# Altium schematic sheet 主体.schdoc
size 297 x 209 mm; Symbol: Drawing-Symbol_A4; @Create Time: 10:59:36; @Update Time: 20:11:28; Border: 1; Width: 1170; Height: 825; Region Start: 1; X Region Count: 6; Y Region Count: 4; Blade Width: 10; Title Block Position: 3; Title Block: 1; @Board Name: Board1; Company: 嘉立创EDA; Version: V1.0; Page Size: A4; @Project Name: stm32f4; @Page Count: 3; @Update Date: 2025-11-17; @Create Date: 2025-10-30; @Schematic Name: Schematic1; @Page No: 1; @Page Name: 主体; Device: Drawing-Symbol_A4
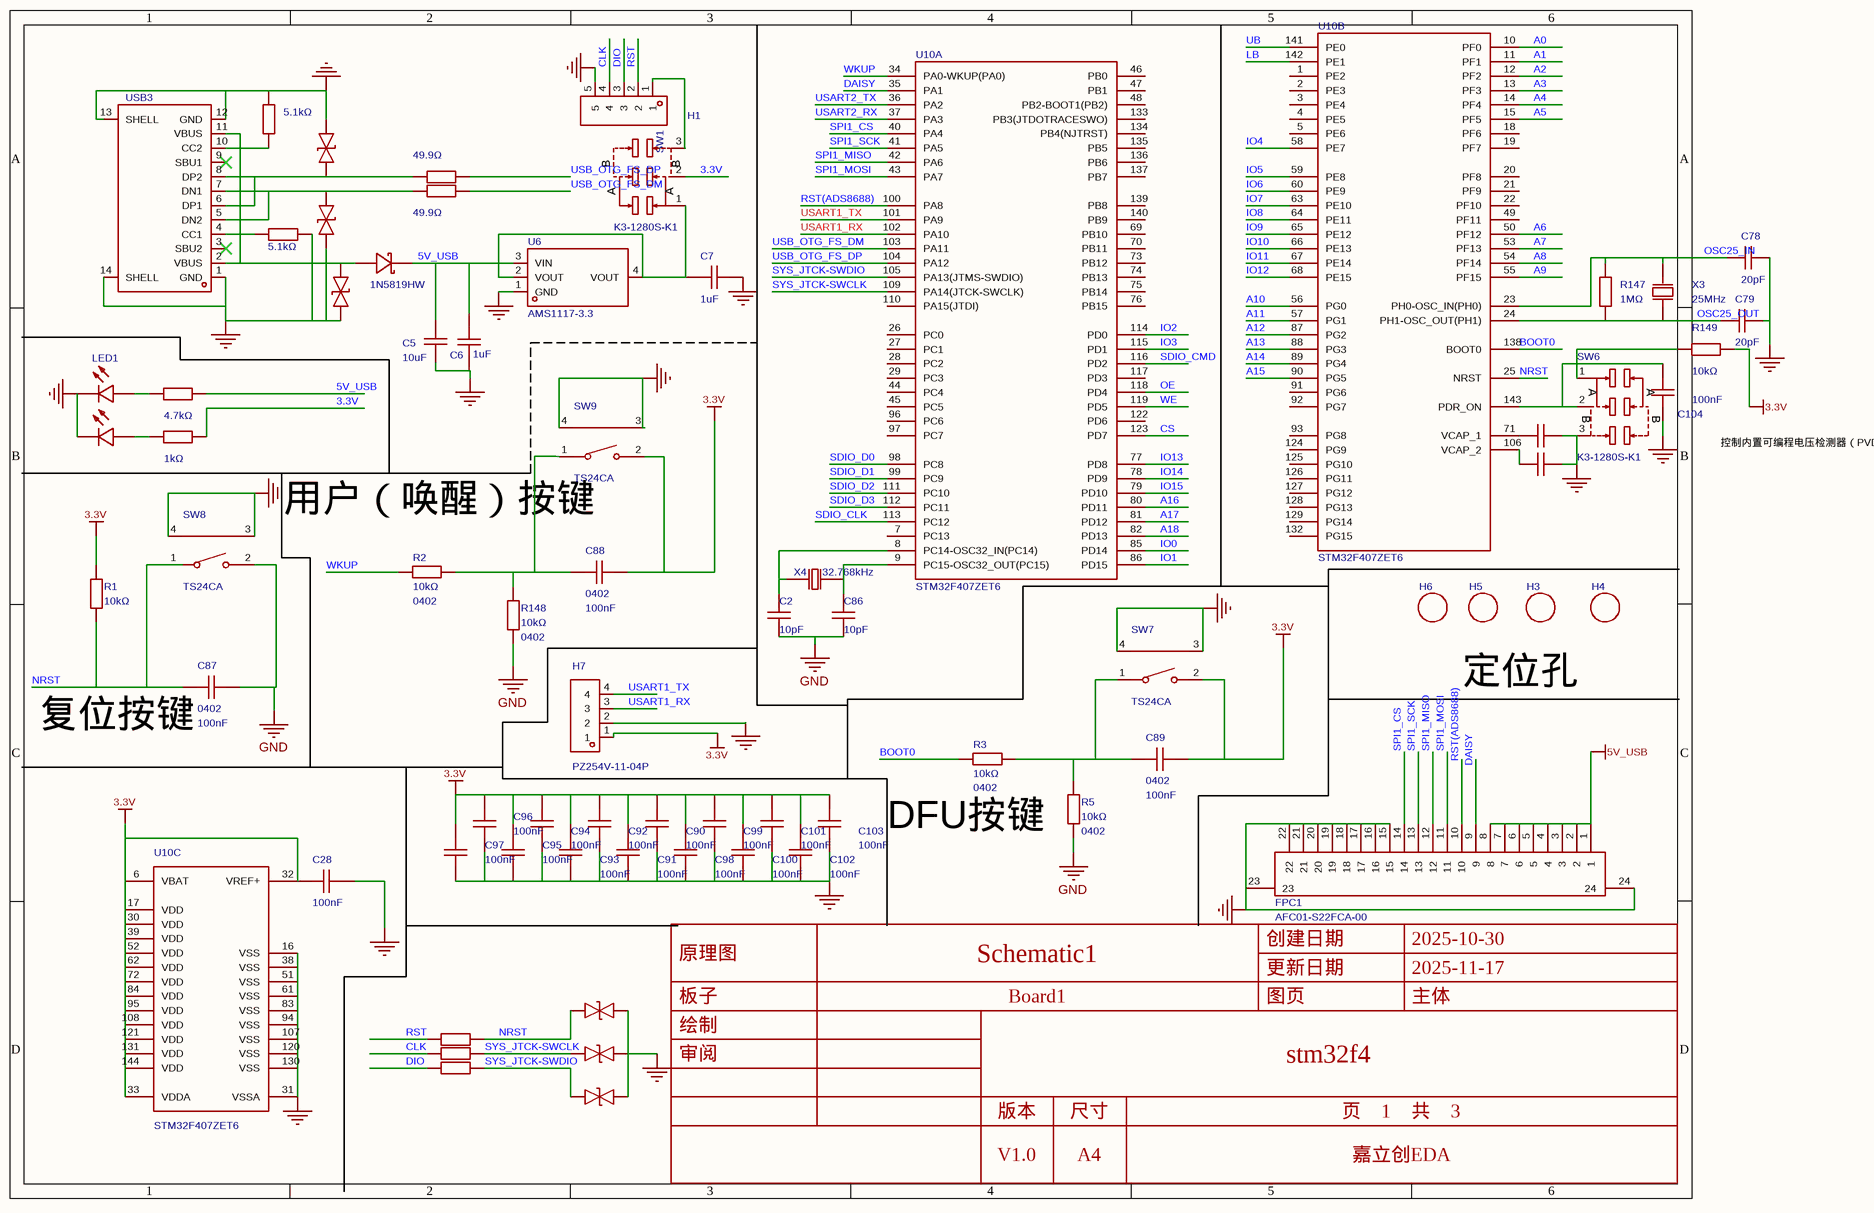
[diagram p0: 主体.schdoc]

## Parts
C2  value 10pF  [r0402]
C5  10uF  [C0603]
C6  1uF  [C0603]
C7  1uF  [C0603]
C28  100nF  [C0603]
C78  20pF  [C0603]
C79  20pF  [C0603]
C80  2.2uF  [C0603]  (value not drawn)
C81  2.2uF  [C0603]  (value not drawn)
C86  value 10pF  [r0402]
C87  value 100nF  Supplier Footprint: 0402  [C0402]  (hidden comment: CC0402KRX7R7BB104)
C88  value 100nF  Supplier Footprint: 0402  [C0402]  (hidden comment: CC0402KRX7R7BB104)
C89  value 100nF  Supplier Footprint: 0402  [C0402]  (hidden comment: CC0402KRX7R7BB104)
C90  100nF  [C0402]
C91  100nF  [C0402]
C92  100nF  [C0402]
C93  100nF  [C0402]
C94  100nF  [C0402]
C95  100nF  [C0402]
C96  100nF  [C0402]
C97  100nF  [C0402]
C98  100nF  [C0402]
C99  100nF  [C0402]
C100  100nF  [C0402]
C101  100nF  [C0402]
C102  100nF  [C0402]
C103  100nF  [C0402]
C104  100nF  [C0402]
D9  0603ESDA-05N  [D0603-BI]  (value not drawn)
D10  0603ESDA-05N  [D0603-BI]  (value not drawn)
D11  0603ESDA-05N  [D0603-BI]  (value not drawn)
D13  LESD5D5.0CT1G  [SOD-523_L1.2-W0.8-LS1.6-BI]  (value not drawn)
D14  LESD5D5.0CT1G  [SOD-523_L1.2-W0.8-LS1.6-BI]  (value not drawn)
D15  LESD5D5.0CT1G  [SOD-523_L1.2-W0.8-LS1.6-BI]  (value not drawn)
D16  1N5819HW  [SOD-123_L2.7-W1.6-LS3.7-RD-1]
FPC1  AFC01-S22FCA-00  [FPC-SMD_P0.5-22P_FGS-XJ-H2.0]
H1  PZ254V-11-05P  [HDR-TH_5P-P2.54-V-M]  (value not drawn)
H3  m3_3  [m3 125x300]  (value not drawn)
H4  m3_3  [m3 125x300]  (value not drawn)
H5  m3_3  [m3 125x300]  (value not drawn)
H6  m3_3  [m3 125x300]  (value not drawn)
H7  PZ254V-11-04P  [HDR-TH_4P-P2.54-V-M]
LED1  19-217/R6C-AL1M2VY/3T  [LED0603-RD]  (value not drawn)
LED5  19-213/Y2C-CQ2R2L/3T(CY)  [LED0603-RD-YELLOW]  (value not drawn)
R1  value 10kΩ  [R0402]  (hidden comment: RC0402FR-0710KL)
R2  value 10kΩ  Supplier Footprint: 0402  [R0402]  (hidden comment: RC0402FR-0710KL)
R3  value 10kΩ  Supplier Footprint: 0402  [R0402]  (hidden comment: RC0402FR-0710KL)
R5  value 10kΩ  Supplier Footprint: 0402  [R0402]  (hidden comment: RC0402FR-0710KL)
R7  49.9Ω  [R0603]  (value not drawn)
R8  49.9Ω  [R0603]  (value not drawn)
R9  49.9Ω  [R0603]  (value not drawn)
R21  value 49.9Ω  [R0603]  (hidden comment: 0603WAF499JT5E)
R22  value 49.9Ω  [R0603]  (hidden comment: 0603WAF499JT5E)
R24  5.1kΩ  [R0402]
R25  5.1kΩ  [R0402]
R26  4.7kΩ  [R0402]
R27  1kΩ  [R0402]
R147  1MΩ  [R0603]
R148  value 10kΩ  Supplier Footprint: 0402  [R0402]  (hidden comment: RC0402FR-0710KL)
R149  10kΩ  [R0402]
SW1  K3-1280S-K1  [SW-SMD_K3-1280S-K1]
SW6  K3-1280S-K1  [SW-SMD_K3-1280S-K1]
SW7  TS24CA  [SW-SMD_2P-TS24CA]
SW8  TS24CA  [SW-SMD_2P-TS24CA]
SW9  TS24CA  [SW-SMD_2P-TS24CA]
U6  AMS1117-3.3  [SOT-223-3_L6.5-W3.4-P2.30-LS7.0-BR]
U10  STM32F407ZET6  [LQFP-144_L20.0-W20.0-P0.50-LS22.0-BL]  (parts A,B,C of 3)
USB3  TYPE-C 16PIN 2MD(073)  [USB-C-SMD_TYPE-C-6PIN-2MD-073]  (value not drawn)
X3  25MHz  [OSC-SMD_L5.0-W3.2]
X4  value 32.768kHz  [crystal-smd_l3.2-w1.5-1]

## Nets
3.3V: C28.1 C88.1 C89.1 C90.1 C91.1 C92.1 C93.1 C94.1 C95.1 C96.1 C97.1 C98.1 C99.1 C100.1 C101.1 C102.1 C103.1 H7.1 R1.1 R27.2 R149.2 SW1.2 SW7.2 SW9.2 U10.6(VBAT) U10.17(VDD) U10.30(VDD) U10.32(VREF+) U10.33(VDDA) U10.39(VDD) U10.52(VDD) U10.62(VDD) U10.72(VDD) U10.84(VDD) U10.95(VDD) U10.108(VDD) U10.121(VDD) U10.131(VDD) U10.144(VDD)
5V_USB: C5.2 C6.2 D16.1(K) FPC1.1 FPC1.2 FPC1.3 FPC1.4 FPC1.5 FPC1.6 FPC1.7 FPC1.8 R26.2 U6.3(VIN)
GND: C2.1 C5.1 C6.1 C7.2 C28.2 C78.1 C79.1 C80.2 C81.2 C86.1 C87.1 C90.2 C91.2 C92.2 C93.2 C94.2 C95.2 C96.2 C97.2 C98.2 C99.2 C100.2 C101.2 C102.2 C103.2 C104.1 D9.2 D10.2 D11.2 D13.1 D14.1 D15.1 FPC1.15 FPC1.16 FPC1.17 FPC1.18 FPC1.19 FPC1.20 FPC1.21 FPC1.22 FPC1.23 FPC1.24 H1.5 H7.2 LED1.1(C) LED5.1(C) R5.2 R24.2 R25.2 R148.2 SW6.3 SW7.3 SW7.4 SW8.2 SW8.3 SW8.4 SW9.3 SW9.4 U6.1(GND) U10.16(VSS) U10.31(VSSA) U10.38(VSS) U10.51(VSS) U10.61(VSS) U10.83(VSS) U10.94(VSS) U10.107(VSS) U10.120(VSS) U10.130(VSS) USB3.1(GND) USB3.12(GND) USB3.13(SHELL) USB3.14(SHELL)
A0: U10.10(PF0)
A1: U10.11(PF1)
A2: U10.12(PF2)
A3: U10.13(PF3)
A4: U10.14(PF4)
A5: U10.15(PF5)
A6: U10.50(PF12)
A7: U10.53(PF13)
A8: U10.54(PF14)
A9: U10.55(PF15)
A10: U10.56(PG0)
A11: U10.57(PG1)
A12: U10.87(PG2)
A13: U10.88(PG3)
A14: U10.89(PG4)
A15: U10.90(PG5)
A16: U10.80(PD11)
A17: U10.81(PD12)
A18: U10.82(PD13)
BOOT0: R3.1 U10.138(BOOT0)
CLK: H1.4 R8.1
CS: U10.123(PD7)
DAISY: FPC1.9 U10.35(PA1)
DIO: H1.3 R9.1
IO0: U10.85(PD14)
IO1: U10.86(PD15)
IO2: U10.114(PD0)
IO3: U10.115(PD1)
IO4: U10.58(PE7)
IO5: U10.59(PE8)
IO6: U10.60(PE9)
IO7: U10.63(PE10)
IO8: U10.64(PE11)
IO9: U10.65(PE12)
IO10: U10.66(PE13)
IO11: U10.67(PE14)
IO12: U10.68(PE15)
IO13: U10.77(PD8)
IO14: U10.78(PD9)
IO15: U10.79(PD10)
LB: U10.142(PE1)
NRST: C87.2 D9.1 R1.2 R7.2 SW8.1 U10.25(NRST)
OE: U10.118(PD4)
OSC25_IN: C78.2 R147.2 U10.23(PH0-OSC_IN(PH0)) X3.2(OSC2)
OSC25_OUT: C79.2 R147.1 U10.24(PH1-OSC_OUT(PH1)) X3.1(OSC1)
RST: H1.2 R7.1
RST(ADS8688): FPC1.10 U10.100(PA8)
SDIO_CLK: U10.113(PC12)
SDIO_CMD: U10.116(PD2)
SDIO_D0: U10.98(PC8)
SDIO_D1: U10.99(PC9)
SDIO_D2: U10.111(PC10)
SDIO_D3: U10.112(PC11)
SPI1_CS: FPC1.14 U10.40(PA4)
SPI1_MISO: FPC1.12 U10.42(PA6)
SPI1_MOSI: FPC1.11 U10.43(PA7)
SPI1_SCK: FPC1.13 U10.41(PA5)
SYS_JTCK-SWCLK: D10.1 R8.2 U10.109(PA14(JTCK-SWCLK))
SYS_JTCK-SWDIO: D11.1 R9.2 U10.105(PA13(JTMS-SWDIO))
UB: U10.141(PE0)
USART1_RX: H7.3 U10.102(PA10)
USART1_TX: H7.4 U10.101(PA9)
USART2_RX: U10.37(PA3)
USART2_TX: U10.36(PA2)
USB_OTG_FS_DM: R22.1 U10.103(PA11)
USB_OTG_FS_DP: R21.1 U10.104(PA12)
WE: U10.119(PD5)
WKUP: R2.1 U10.34(PA0-WKUP(PA0))
NetC2_2: C2.2 U10.8(PC14-OSC32_IN(PC14)) X4.1
NetC7_1: C7.1 SW1.1 U6.2(VOUT) U6.4(VOUT)
NetC80_1: C80.1 U10.71(VCAP_1)
NetC81_1: C81.1 U10.106(VCAP_2)
NetC86_2: C86.2 U10.9(PC15-OSC32_OUT(PC15)) X4.2
NetC88_2: C88.2 R2.2 R148.1 SW9.1
NetC89_2: C89.2 R3.2 R5.1 SW7.1
NetC104_2: C104.2 SW6.2 U10.143(PDR_ON)
NetD13_2: D13.2 R21.2 USB3.6(DP1) USB3.8(DP2)
NetD14_2: D14.2 R22.2 USB3.5(DN2) USB3.7(DN1)
NetD15_2: D15.2 D16.2(A) USB3.2(VBUS) USB3.11(VBUS)
NetH1_1: H1.1 SW1.3
NetLED1_2: LED1.2(A) R26.1
NetLED5_2: LED5.2(A) R27.1
NetR24_1: R24.1 USB3.10(CC2)
NetR25_1: R25.1 USB3.4(CC1)
NetR149_1: R149.1 SW6.1

Not connected (* = marked no-connect by the designer): U10 1(PE2) 2(PE3) 3(PE4) 4(PE5) 5(PE6) 7(PC13) 18(PF6) 19(PF7) 20(PF8) 21(PF9) 22(PF10) 26(PC0) 27(PC1) 28(PC2) 29(PC3) 44(PC4) 45(PC5) 46(PB0) 47(PB1) 48(PB2-BOOT1(PB2)) 49(PF11) 69(PB10) 70(PB11) 73(PB12) 74(PB13) 75(PB14) 76(PB15) 91(PG6) 92(PG7) 93(PG8) 96(PC6) 97(PC7) 110(PA15(JTDI)) 117(PD3) 122(PD6) 124(PG9) 125(PG10) 126(PG11) 127(PG12) 128(PG13) 129(PG14) 132(PG15) 133(PB3(JTDOTRACESWO)) 134(PB4(NJTRST)) 135(PB5) 136(PB6) 137(PB7) 139(PB8) 140(PB9); USB3 3(SBU2)* 9(SBU1)*

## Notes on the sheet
- 控制内置可编程电压检测器（PVD）的开启/关闭
- 用户（唤醒）按键
- 定位孔
- 复位按键
- DFU按键

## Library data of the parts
C2 C86 = CC0402JRNPO9BN100: 容值:10pF;精度:±5%;额定电压:50V;温度系数:NP0;; Manufacturer: YAGEO(国巨); AddInBom: yes; ModelId: 36a51122f27c49738f86b3bfa98863e0; ModelName: C0402_L1.0-W0.5-H0.5; ModelTransform: 39.37,19.685,0,0,0,0,0,0,0; Tolerance: ±5%; Voltage Rated: 50V; Temperature Coefficient: NP0
C5 = 0603X106K100NT: 容值:10uF;精度:±10%;额定电压:10V;材质(温度系数):X5R;; Manufacturer: FH(风华); AddInBom: yes; ModelId: ac125912035d415993ca9572d50418b1; ModelName: C0603_L1.6-W0.8-H0.8; ModelTransform: 62.992,31.496,0,0,0,0,0,0,0; Tolerance: ±10%; Voltage Rated: 10V; Temperature Coefficient: X5R
C6 C7 = CL10A105KB8NNNC: 容值:1uF;精度:±10%;额定电压:50V;温度系数:X5R;; Manufacturer: SAMSUNG(三星); AddInBom: yes; ModelId: ac125912035d415993ca9572d50418b1; ModelName: C0603_L1.6-W0.8-H0.8; ModelTransform: 62.992,31.496,0,0,0,0,0,0,0; Tolerance: ±10%; Voltage Rating: 50V; Temperature Coefficient: X5R
C28 = CC0603KRX7R9BB104: 容值:100nF;精度:±10%;额定电压:50V;材质(温度系数):X7R;; Manufacturer: YAGEO(国巨); Voltage Rating: 50V; AddInBom: yes; ModelId: ac125912035d415993ca9572d50418b1; ModelName: C0603_L1.6-W0.8-H0.8; ModelTransform: 62.992,31.496,0,0,0,0,0,0,0; Tolerance: ±10%; Temperature Coefficient: X7R
C78 C79 = CL10C200JB8NNNC: 容值:20pF;精度:±5%;额定电压:50V;温度系数:C0G;; Manufacturer: SAMSUNG(三星); AddInBom: yes; ModelId: ac125912035d415993ca9572d50418b1; ModelName: C0603_L1.6-W0.8-H0.8; ModelTransform: 62.992,31.496,0,0,0,0,0,0,0; Tolerance: ±5%; Voltage Rating: 50V; Temperature Coefficient: C0G
C80 C81 = CL10A225KO8NNNC: 容值:2.2uF;精度:±10%;额定电压:16V;温度系数:X5R;; Manufacturer: SAMSUNG(三星); AddInBom: yes; ModelId: ac125912035d415993ca9572d50418b1; ModelName: C0603_L1.6-W0.8-H0.8; ModelTransform: 62.992,31.496,0,0,0,0,0,0,0; Tolerance: ±10%; Voltage Rating: 16V; Temperature Coefficient: X5R
C87-C89 C104 = CC0402KRX7R7BB104: 容值:100nF;精度:±10%;额定电压:16V;材质(温度系数):X7R;; Manufacturer: YAGEO(国巨); AddInBom: yes; ModelId: 36a51122f27c49738f86b3bfa98863e0; ModelName: C0402_L1.0-W0.5-H0.5; ModelTransform: 39.37,19.685,0,0,0,0,0,0,0; Tolerance: ±10%; Voltage Rated: 16V; Temperature Coefficient: X7R
C90-C103 = CL05B104KB54PNC: 容值:100nF;精度:±10%;额定电压:50V;温度系数:X7R;; Manufacturer: SAMSUNG(三星); AddInBom: yes; ModelId: 36a51122f27c49738f86b3bfa98863e0; ModelName: C0402_L1.0-W0.5-H0.5; ModelTransform: 39.37,19.685,0,0,0,0,0,0,0; Tolerance: ±10%; Voltage Rating: 50V; Temperature Coefficient: X7R
D9-D11 = 0603ESDA-05N: 极性:双向;反向截止电压(Vrwm):5V;钳位电压:50V;; Manufacturer: BORN(伯恩半导体); AddInBom: yes; ModelId: a387ce2936f842ebafc868b09fdf8ecc; ModelName: DO0603_L1.6-W0.8-H0.8-LS1.6; ModelTransform: 62.992,31.496,0,0,0,0,0,0,0; Polarity: 双向; Reverse Stand-Off Voltage (Vrwm): 5V; Clamping Voltage: 50V; Reverse Leakage Current (Ir): 500nA; level of protection: IEC 61000-4-2; Type: ESD; Junction Capacitance: 1.5pF
D13-D15 = LESD5D5.0CT1G: 极性:双向;反向截止电压(Vrwm):5V;钳位电压:18.6V;峰值脉冲电流(Ipp):9.4A@8/20us;峰值脉冲功率(Ppp):150W@8/20us;击穿电压:7.8V;; Manufacturer: LRC(乐山无线电); AddInBom: yes; ModelId: bfbc20aaa9964d25bc07bd43d1c87046; ModelTransform: 62.992,31.496,0,0,0,0,0,0,0; Polarity: 双向; Reverse Stand-Off Voltage (Vrwm): 5V; Clamping Voltage: 18.6V; Voltage - Breakdown: 7.8V; Reverse Leakage Current (Ir): 1uA; level of protection: IEC 61000-4-4；IEC 61000-4-2; Type: ESD; Junction Capacitance: 15pF
D16 = 1N5819HW: 二极管配置:-;正向压降(Vf):900mV@3A;直流反向耐压(Vr):40V;整流电流:1A;; Manufacturer: TECH PUBLIC(台舟); AddInBom: yes; ModelId: 528459655f7d4601a76356f3191c812b; ModelTransform: 151.575,66.929,0,0,0,0,0,0,0; Voltage - DC Reverse(Vr): 40V; Current - Rectified: 1A; Reverse Leakage Current (Ir): 1mA@40V; Non-Repetitive Peak Forward Surge Current: 9A
FPC1 = AFC01-S22FCA-00: 锁定特性:翻盖式;触点类型:下接;触点数量:22P;间距:0.5mm;安装类型:卧贴;; Manufacturer: JS(钜硕电子); AddInBom: yes; ModelId: 12d9165dec84425d968f174b1be8289a; ModelTransform: 610.235,240.157,0,0,0,0,0,57.008,0; Locking Feature: 翻盖式; Number of Contacts: 22P; Pitch: 0.5mm; FFC, FCB Thickness: 0.3mm
H1 = PZ254V-11-05P: 插针结构:1x5P;间距:2.54mm;行距:-;圆针/方针:方针;安装方式:直插;排数:单排;总PIN位数:5P;额定电流:-;额定电压:-;配合针长度:6mm;塑高:2.5mm;端接针长度:3mm;触头材质:黄铜;触头镀层:-;工作温度:-40℃~+105℃;颜色:黑色;; Manufacturer: XFCN(兴飞); AddInBom: yes; ModelId: 47d466e4a34f4fc5bc626cf773a24dd5; ModelName: HDR-TH_5P-P2.54-M-LI-1X5P; ModelTransform: 499.999,100,0,0,0,0,0,0,-118.11; Pin Structure: 1x5P; Pitch: 2.54mm; Circluar Pins/Square Pins: 方针
H3-H6 = m3_3: Symbol: m3; AddInBom: yes
H7 = PZ254V-11-04P: 插针结构:1x4P;间距:2.54mm;行距:-;圆针/方针:方针;安装方式:直插;排数:单排;总PIN位数:4P;额定电流:3A;额定电压:250V;配合针长度:6mm;塑高:2.5mm;端接针长度:3mm;触头材质:-;工作温度:-40℃~+105℃;颜色:黑色;; Manufacturer: XFCN(兴飞); Symbol: PZ254V-11-04P_C2691448; AddInBom: yes; ModelId: 112f4d05e8d64e99ab9a333894bea4f9; ModelName: HDR-TH_4P-P2.54-M-LI-1X4P; ModelTransform: 399.999,104.7242,0,0,0,0,0,0,-118.11; Pin Structure: 1x4P; Pitch: 2.54mm; Circluar Pins/Square Pins: 方针; Current Rating: 3A; Voltage Rating (Max): 250V
LED1 = 19-217/R6C-AL1M2VY/3T: 发光颜色:红色;正向压降(Vf):1.95V;功率:60mW;正向电流:5mA;波长:617.5nm;二极管配置:-;透镜颜色:无色透明透镜;色温:-;发光角度:120°;载带方式:-;工作温度:-40℃~+85℃;; Manufacturer: EVERLIGHT(亿光); AddInBom: yes; ModelId: 1f0d29a91be547639d425604e9b96ebb; ModelTransform: 63.7794,32.283,0,0,0,0,0,0,0; Illumination Color: 红色; Voltage - Forward(Vf): 1.95V; Power(Watts): 60mW; Forward Current: 5mA; Peak Wavelength: 632nm; Lens Color: 无色透明透镜; Viewing Angle: 120°
LED5 = 19-213/Y2C-CQ2R2L/3T(CY): 发光颜色:黄灯;二极管配置:-;主波长:585.5nm~591.5nm;色温:-;功率:60mW;安装方式:-;; Manufacturer: EVERLIGHT(亿光); AddInBom: yes; ModelId: a8fc7d5425514cf49dd600af0a7bb223; ModelTransform: 63.7794,32.283,0,0,0,0,-1.969,0,0; Emitted Color: 黄灯; Lens Color: 无色透明; Peak Wavelength: 591nm; Forward Current: 20mA; Power Dissipation: 60mW; Viewing Angle: 120°
R1-R3 R5 R148 = RC0402FR-0710KL: 电阻类型:厚膜电阻;阻值:10kΩ;精度:±1%;功率:62.5mW;; Manufacturer: YAGEO(国巨); AddInBom: yes; ModelId: 671aefced39d4c318694bba8bd8efd39; ModelName: R0402_L1.0-W0.5-H0.5; ModelTransform: 39.37,19.685,0,0,0,0,0,0.0005,0; Tolerance: ±1%; Power(Watts): 62.5mW; Temperature Coefficient: ±100ppm/℃; Overload Voltage (Max): 50V
R7-R9 R21 R22 = 0603WAF499JT5E: 电阻类型:厚膜电阻;阻值:49.9Ω;精度:±1%;功率:100mW;工作电压:75V;温度系数:±100ppm/℃;; Manufacturer: UNI-ROYAL(厚声); AddInBom: yes; ModelId: fc143cca1e79419f9cd78b61e9279f08; ModelTransform: 31.8897,63.7794,0,90,0,0,0,0,0; Tolerance: ±1%; Power(Watts): 100mW; Voltage-Supply(Max): 75V
R24 R25 = 0402WGF5101TCE: 电阻类型:厚膜电阻;阻值:5.1kΩ;精度:±1%;功率:62.5mW;工作电压:50V;温度系数:±100ppm/℃;; Manufacturer: UNI-ROYAL(厚声); AddInBom: yes; ModelId: 98c88bc2b9094f218f3a3e30a7012738; ModelName: R0402_L1.0-W0.5-H0.4; ModelTransform: 39.37,19.685,0,0,0,0,0,0,0; Tolerance: ±1%; Power(Watts): 62.5mW; Voltage-Supply(Max): 50V
R26 = 0402WGF4701TCE: 电阻类型:厚膜电阻;阻值:4.7kΩ;精度:±1%;功率:62.5mW;工作电压:50V;温度系数:±100ppm/℃;; Manufacturer: UNI-ROYAL(厚声); AddInBom: yes; ModelId: 98c88bc2b9094f218f3a3e30a7012738; ModelName: R0402_L1.0-W0.5-H0.4; ModelTransform: 39.37,19.685,0,0,0,0,0,0,0; Tolerance: ±1%; Power(Watts): 62.5mW; Voltage-Supply(Max): 50V
R27 = 0402WGF1001TCE: 电阻类型:厚膜电阻;阻值:1kΩ;精度:±1%;功率:62.5mW;工作电压:50V;温度系数:±100ppm/℃;; Manufacturer: UNI-ROYAL(厚声); AddInBom: yes; ModelId: 98c88bc2b9094f218f3a3e30a7012738; ModelName: R0402_L1.0-W0.5-H0.4; ModelTransform: 39.37,19.685,0,0,0,0,0,0,0; Tolerance: ±1%; Power(Watts): 62.5mW; Voltage-Supply(Max): 50V
R147 = 0603WAF1004T5E: 电阻类型:厚膜电阻;阻值:1MΩ;精度:±1%;功率:100mW;最大工作电压:75V;温度系数:±100ppm/℃;; Manufacturer: UNI-ROYAL(厚声); AddInBom: yes; ModelId: fc143cca1e79419f9cd78b61e9279f08; ModelTransform: 31.8897,63.7794,0,90,0,0,0,0,0; Tolerance: ±1%; Power(Watts): 100mW; Overload Voltage (Max): 75V
R149 = 0402WGF1002TCE: 电阻类型:厚膜电阻;阻值:10kΩ;精度:±1%;功率:62.5mW;工作电压:50V;温度系数:±100ppm/℃;; Manufacturer: UNI-ROYAL(厚声); AddInBom: yes; ModelId: 98c88bc2b9094f218f3a3e30a7012738; ModelName: R0402_L1.0-W0.5-H0.4; ModelTransform: 39.37,19.685,0,0,0,0,0,0,0; Tolerance: ±1%; Power(Watts): 62.5mW; Voltage-Supply(Max): 50V
SW1 SW6 = K3-1280S-K1: 电路结构:单刀双掷;安装方式:卧贴;开关颜色:黑色;额定电流:300mA;额定电压:6V;工作寿命:1万次;; Manufacturer: 韩国韩荣; AddInBom: yes; ModelId: ab25a683fa8b4ba5906172fee6c197a1; ModelTransform: 295.275,358.267,0,0,0,0,133.05,0,-23.622; Circuit: 单刀双掷; Actuator Style: 矩形柱状; Switch Height: 3.5mm; Actuator Color: 黑色; Current Rating: 300mA; Voltage Rating: 6V; Life: 1万次
SW7-SW9 = TS24CA: 电路结构:单刀单掷;按钮形状:矩形按钮;安装方式:卧贴;开关长度:4.55mm;开关宽度:1.8mm;开关高度:3.5mm;触点电流:50mA;额定电压:12V;带灯:-;工作寿命:-;; Manufacturer: SHOU HAN(首韩); AddInBom: yes; ModelId: 40fd58424abd4d6abbbb880ec41c542e; ModelTransform: 185.039,142.9131,0,0,0,0,0,26.929,-15.748; Circuit: 单刀单掷; Actuator Style: 矩形按钮; Switch Height: 3.5mm; Contact Current: 50mA; Voltage Rating: 12V
U6 = AMS1117-3.3_C6186: 输出类型:固定;工作电压:16V;输出电压:3.3V;输出电流:1A;电源纹波抑制比(PSRR):72dB@(120Hz);输出极性:正极;; Manufacturer: AMS; AddInBom: yes; ModelId: 925194bf9823436183a3e0b978a8d076; ModelName: SOT-223-4P_L6.5-W3.5-H1.6-LS7.0-P2.30; ModelTransform: 279.89794,255.905,0,180,0,0,-3.9385,-0.0005,0; Output Type: 固定; Voltage - Supply: 16V; Output Voltage: 3.3V; Output Current: 1A; Voltage Dropout: 1.1V@(800mA); standby current: 5mA; Noise: 0.003%Vout; Output Configuration: 正极; Number of Outputs: 1
U10 = STM32F407ZET6: CPU位数:32-Bit;ROM类型:FLASH;CPU内核:ARM® Cortex®-M4;主频（MAX):168MHz;工作电压:1.8V ~ 3.6V;; Manufacturer: ST(意法半导体); Relevance: []; AddInBom: yes; ModelId: 46049659436c43e8bd1e5c2b84034010; ModelName: LQFP-144_L20.0-W20.0-H1.4-LS22.0-P0.50; ModelTransform: 866.36,866.36,0,0,0,0,0.002,-0.001,0; Core Size: 32-Bit; Program Memory Type: FLASH; Speed: 168MHz; Program Memory Size: 512KB; RAM Size: 192KB; Number of I/O: 114; A/D: 24x12bit; D/A: 2x12bit; PWM: 56; LCD: MOTOROLA 6800 AND INTEL  8080 TYPE LCD DIRECTLY; UART/USART: 4 USART+2 UART; SPI: 3; USB Device: 1; CAN: 2; Ethernet: 10/100 Ethernet MAC
USB3 = TYPE-C 16PIN 2MD(073): 连接器类型:Type-C;协议标准:-;公母:母;安装方式:卧贴;触点数量:16P;端口数量:1;额定电流 - 电源:3A;工作温度:-25℃~+85℃;; Manufacturer: SHOU HAN(首韩); AddInBom: yes; ModelId: 3a41b9ec9b654a0fad4d118405ec6290; ModelTransform: 351.9678,298.4246,0,0,0,0,0,-47.244,-35.433; Gender: 母; Number of Contacts: 16P; Number of Ports: 1; Current Rating-Power: 3A; Voltage Rating: 5V; Connect-Disconnect Life: 5千次; Detection color: 黑色
X3 = X503225MSB2GI: 晶振类型:贴片晶振;频率:25MHz;常温频差:±10ppm;负载电容:20pF;频率稳定度:±20ppm;; Manufacturer: YXC(扬兴晶振); AddInBom: yes; ModelId: 36c8b961b9064b60a7c920ab5154e867; ModelName: OSC-SMD_L5.0-W3.2-H1.4; ModelTransform: 196.85,126.023,0,0,0,0,0,0,0; Normal temperature Frequency Tolerance: ±10ppm; Load Capacitance: 20pF; Frequency Stability: ±20ppm
X4 = FC31M2-32.768-NTLLLDT: 晶振类型:贴片无源晶振;频率:32.768kHz;频率公差:±20ppm;频率稳定度:±20ppm;负载电容:12.5pF;等效串联电阻(ESR):50kΩ;工作温度:-40~+85;; Manufacturer: HCI(杭晶); AddInBom: yes; ModelId: 762d7afc596f4558a373612390f4386d; ModelTransform: 126,59.1,0,0,0,0,0,0,0; Crystal Type: 贴片无源晶振; Load Capacitance: 12.5pF; Frequency Tolerance: ±20ppm; Equivalent Series Resistance (ESR): 50kΩ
